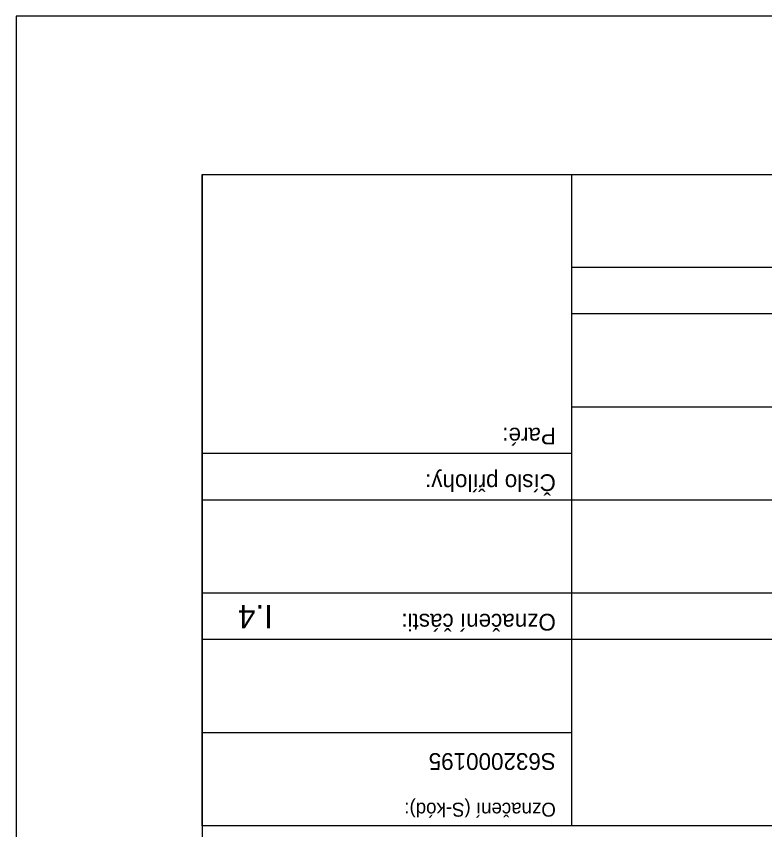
# Model space of a CAD drawing. Extents: x -728476.8 to -728424.3, y -1073086.9 to -1073012.7.
# Drawn here: x -728476.79 to -728456.69, y -1073034.51 to -1073012.65 of the extents above; entities that cross this region are included whole.
import ezdxf

# ---------------------------------------------------------------- set-up
doc = ezdxf.new("R2010")
doc.units = 0
for name, color, linetype in [('_NOR-šraf_+6', 7, 'Continuous'), ('Default', 7, 'Continuous'), ('ZZZ_popisky', 7, 'Continuous')]:
    doc.layers.add(name, color=color, linetype=linetype)

msp = doc.modelspace()

# ---------------------------------------------------------------- linework, layer by layer
at = {"layer": '_NOR-šraf_+6'}
for p, q in [((-728429.292, -1073019.404), (-728461.879, -1073019.404)), ((-728429.292, -1073020.654), (-728461.879, -1073020.654)), ((-728429.292, -1073023.154), (-728461.879, -1073023.154)), ((-728461.879, -1073024.404), (-728471.792, -1073024.404)), ((-728461.879, -1073025.654), (-728471.792, -1073025.654)), ((-728429.292, -1073025.654), (-728461.879, -1073025.654)), ((-728461.879, -1073028.154), (-728471.792, -1073028.154)), ((-728429.292, -1073028.154), (-728461.879, -1073028.154)), ((-728461.879, -1073029.404), (-728471.792, -1073029.404)), ((-728429.292, -1073029.404), (-728461.879, -1073029.404)), ((-728461.879, -1073031.904), (-728471.792, -1073031.904))]:
    msp.add_line(p, q, dxfattribs=at)
for points in [[(-728471.792, -1073016.904), (-728461.879, -1073016.904), (-728461.879, -1073034.404), (-728471.792, -1073034.404)], [(-728429.288, -1073034.404), (-728471.788, -1073034.404), (-728471.788, -1073016.904), (-728429.288, -1073016.904)]]:
    msp.add_lwpolyline(points, close=True, dxfattribs=at)
at = {"layer": 'Default'}
msp.add_lwpolyline([(-728424.288, -1073012.654), (-728476.788, -1073012.654), (-728476.788, -1073086.904), (-728424.288, -1073086.904)], close=True, dxfattribs=at)
msp.add_lwpolyline([(-728424.288, -1073012.654), (-728476.788, -1073012.654), (-728476.788, -1073086.904), (-728424.288, -1073086.904)], close=True, dxfattribs=at)
at = {"layer": 'ZZZ_popisky'}
msp.add_lwpolyline([(-728429.288, -1073081.904), (-728471.788, -1073081.904), (-728471.788, -1073016.904), (-728429.288, -1073016.904)], close=True, dxfattribs=at)

# ---------------------------------------------------------------- texts
at = {"layer": '_NOR-šraf_+6'}
for s, height, p in [('Paré:', 0.45, (-728462.298, -1073023.71)), ('Číslo přílohy:', 0.45, (-728462.298, -1073024.96)), ('I.4 ', 0.625, (-728469.9, -1073028.473)), ('Označení části:', 0.45, (-728462.298, -1073028.71)), ('S632000195', 0.45, (-728462.298, -1073032.454)), ('Označení (S-kód):', 0.375, (-728462.298, -1073033.785))]:
    msp.add_text(s, height=height, rotation=180, dxfattribs=at).set_placement(p)

doc.saveas('drawing.dxf')
